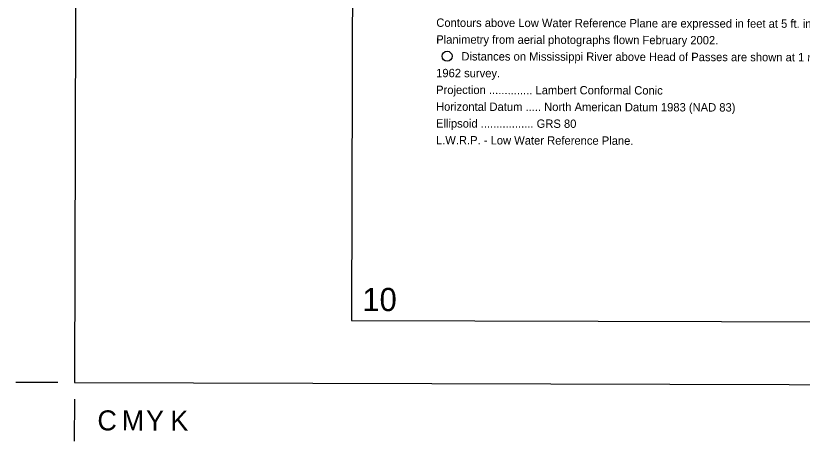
# Model space of a CAD drawing. Extents: x 3161564 to 3199464, y 849354 to 874788.
# Drawn here: x 3161564 to 3169375, y 849455 to 853682 of the extents above; entities that cross this region are included whole.
import ezdxf

# ---------------------------------------------------------------- set-up
doc = ezdxf.new("R2010")
doc.units = 0
for name, color, linetype in [('G-ANNO-NPLT', 7, 'Continuous'), ('V-ANNO-DIMS', 7, 'Continuous'), ('V-ANNO-NOTE', 7, 'Continuous'), ('V-ANNO-SYMB', 7, 'Continuous'), ('V-ANNO-TEXT', 7, 'Continuous')]:
    doc.layers.add(name, color=color, linetype=linetype)

msp = doc.modelspace()

# ---------------------------------------------------------------- linework, layer by layer
at = {"layer": 'G-ANNO-NPLT'}
msp.add_lwpolyline([(3162147.8, 850038.3), (3198814.3, 849937), (3198881.1, 874103.6), (3162214.6, 874204.9)], close=True, dxfattribs=at)
at = {"layer": 'V-ANNO-DIMS'}
for p, q in [((3161981.1, 850038.8), (3161564.5, 850039.9)), ((3162147.3, 849871.6), (3162146.2, 849455))]:
    msp.add_line(p, q, dxfattribs=at)
at = {"layer": 'V-ANNO-NOTE'}
msp.add_circle((3165848.3, 853279.2), 50, dxfattribs=at)
at = {"layer": 'V-ANNO-SYMB'}
msp.add_lwpolyline([(3164899.6, 850655.7), (3197982.7, 850564.3), (3198046, 873480.8), (3164963, 873572.2), (3164899.6, 850655.7)], dxfattribs=at)

# ---------------------------------------------------------------- texts
at = {"layer": 'V-ANNO-DIMS'}
for s, p in [('C', (3162375.4, 849563)), ('M', (3162617.1, 849562.4)), ('Y', (3162858.8, 849561.7)), ('K', (3163100.4, 849561))]:
    msp.add_text(s, height=199.3, rotation=359.84166, dxfattribs=at).set_placement(p)
at = {"layer": 'V-ANNO-NOTE'}
for s, rotation, p in [('Contours above Low Water Reference Plane are expressed in feet at 5 ft. intervals.', 359.84167, (3165740.9, 853571.4)), ('Planimetry from aerial photographs flown February 2002.', 359.84167, (3165740.4, 853404.7)), ('Distances on Mississippi River above Head of Passes are shown at 1 mile intervals,', 359.84167, (3165990.1, 853237.3)), ('1962 survey.', 359.84167, (3165739.5, 853071.3)), ('Projection .............. Lambert Conformal Conic', 359.84164, (3165739, 852904.6)), ('Horizontal Datum ..... North American Datum 1983 (NAD 83)', 359.84164, (3165738.6, 852737.9)), ('Ellipsoid ................. GRS 80', 359.84164, (3165738.1, 852571.2)), ('L.W.R.P. - Low Water Reference Plane.', 359.84164, (3165737.6, 852404.6))]:
    msp.add_text(s, height=83, rotation=rotation, dxfattribs=at).set_placement(p)
at = {"layer": 'V-ANNO-TEXT'}
msp.add_text('10', height=230, rotation=359.84167, dxfattribs=at).set_placement((3165006.3, 850748.8))

doc.saveas('drawing.dxf')
